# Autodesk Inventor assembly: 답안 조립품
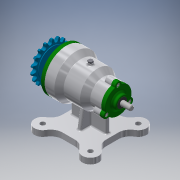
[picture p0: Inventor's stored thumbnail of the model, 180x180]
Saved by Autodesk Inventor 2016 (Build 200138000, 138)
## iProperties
Created: 2017-03
Part Number: 답안 조립품
Material: 일반
Document SubType Name: Assembly
Designer: USER
Author: USER
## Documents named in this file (14)
- C:\Users\USER\Desktop\470308V1006\답안 조립품.iam
- C:\Users\USER\Desktop\470308V1006\본체.ipt
- C:\Users\USER\Desktop\470308V1006\뒤커버.ipt
- C:\Users\USER\Desktop\470308V1006\베어링-6200.ipt
- C:\Users\USER\Desktop\470308V1006\베어링-6203.ipt
- C:\Users\USER\Desktop\470308V1006\볼트 M4 x 12.ipt
- C:\Users\USER\Desktop\470308V1006\볼트 M5 x 10.ipt
- 볼트 M5 x 10.ipt
- C:\Users\USER\Desktop\470308V1006\스프로킷.ipt
- C:\Users\USER\Desktop\470308V1006\앞커버.ipt
- C:\Users\USER\Desktop\470308V1006\오일 실 10 20 7.ipt
- C:\Users\USER\Desktop\470308V1006\오일 실 17 30 8.ipt
- C:\Users\USER\Desktop\470308V1006\축.ipt
- C:\Users\USER\Desktop\470308V1006\키5x5.ipt
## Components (10 placed, 1 different names)
1. ISO 4762 M4 x 12:1
2. ISO 4762 M4 x 12:3
3. ISO 4762 M4 x 12:4
4. ISO 4762 M4 x 12:5
5. ISO 4762 M4 x 12:2
6. ISO 4762 M4 x 12:7
7. ISO 4762 M4 x 12:8
8. ISO 4762 M4 x 12:9
9. ISO 4762 M4 x 12:10
10. ISO 4762 M4 x 12:11
